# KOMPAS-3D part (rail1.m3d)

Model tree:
1. X Axis
2. Y Axis
3. Z Axis
4. Origin  (labels: D:\Program Files\ASCON\KOMPAS-3D V10\Sys\GRAPHIC_EN.LYT; Rail 01)
     Wall Thickness 1 = 1; Wall Thickness 2 = 1; Distance 1 = 50; Distance 2 = 10

Referenced files in D:\Documents and Settings\kashirsky\Рабочий стол\My sample\: Base plate.a3d
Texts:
  Rail 01
  Rail of BP
  Three Point Plane
  Plane at Angle
  Line and Point Plane
  Axis through Two Vertices
  Axis of Feature
  Axis of Conical Surface
  Axis through Edge
  Trim by Surface
  Trim by Sketch
  Feature with No History
  Intersection Axis of Two Planes
  Two Line Plane
  Line and Face Plane
  Bend by line
  Hole in sheet body
  Cut in sheet body
  Point in CM
  Linear Dimension from Line to Point
  Surface Finish Symbol
  Geometric Tolerance Symbol
  Leader #1
  Leader #2
  Leader #3
  Shape Deviations and Datum
  Node point number
  Mark of coordination axis
  Node point designation
  Mark/Reference designation with leader
  Mark/reference designation on line
  Mark/Reference designation without leader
